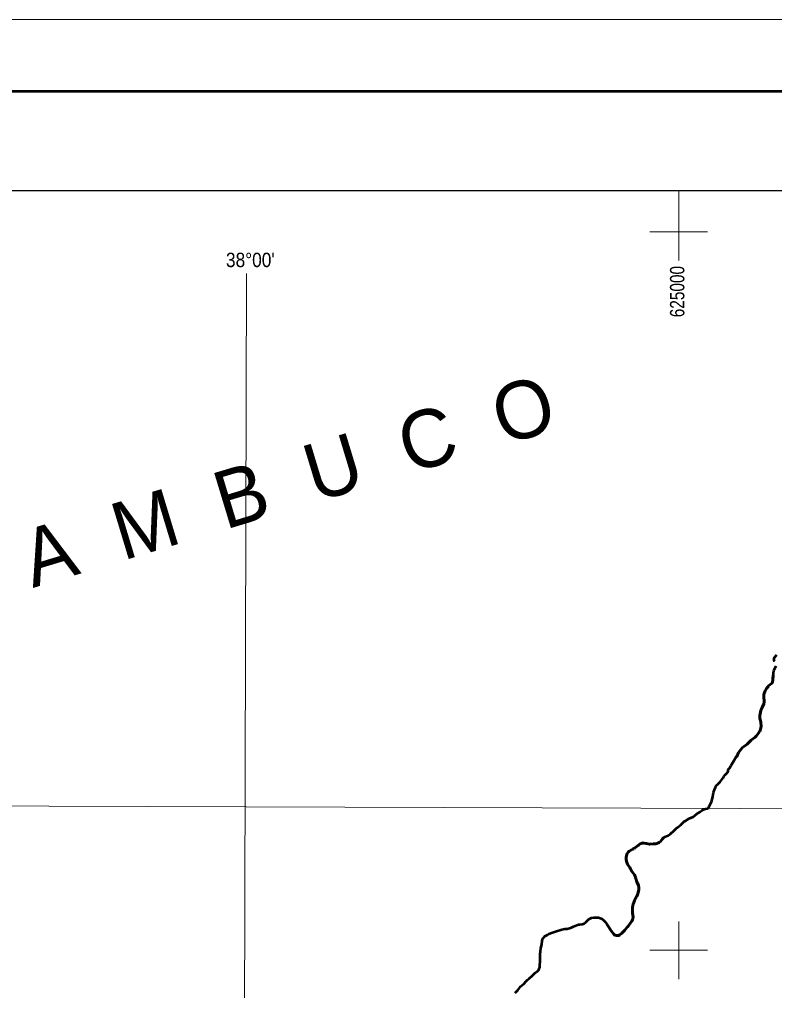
# Model space of a CAD drawing. Extents: x 553962 to 842807, y 8883888 to 9032388.
# Drawn here: x 602069 to 628336, y 8998597 to 9032388 of the extents above; entities that cross this region are included whole.
import ezdxf
from ezdxf.enums import TextEntityAlignment as Align

# ---------------------------------------------------------------- set-up
doc = ezdxf.new("R2010")
doc.units = 0
doc.header["$LTSCALE"] = 20
doc.linetypes.add('LONG_DASH_SHORT_DASH', pattern=[9.9, 6, -1.2, 1.5, -1.2])
for name, color, linetype, lineweight in [('1', 7, 'Continuous', 13), ('2', 7, 'Continuous', 13), ('24', 7, 'Continuous', 25), ('3', 7, 'Continuous', 13), ('7', 7, 'LONG_DASH_SHORT_DASH', 60)]:
    doc.layers.add(name, color=color, linetype=linetype, lineweight=lineweight)
for name, color, linetype in [('42', 7, 'Continuous'), ('46', 7, 'Continuous'), ('47', 7, 'Continuous')]:
    doc.layers.add(name, color=color, linetype=linetype)

msp = doc.modelspace()

# ---------------------------------------------------------------- linework, layer by layer
at = {"layer": '1'}
for points in [[(609971.86, 9023551.79), (609764.7, 8949706.73), (609734.23, 8939404.42)], [(565303.24, 9005146.57), (664889.8, 9004806.7), (719872.1, 9004543.9), (790635.75, 9004109.02)]]:
    msp.add_lwpolyline(points, dxfattribs=at)
at = {"layer": '2'}
for p, q in [((625000, 9024000), (625000, 9026438.81)), ((624000, 9025000), (626000, 9025000)), ((625000, 8999000), (625000, 9001000)), ((624000, 9000000), (626000, 9000000))]:
    msp.add_line(p, q, dxfattribs=at)
at = {"layer": '24', "lineweight": 53}
for points in [[(628342.78, 9010045.26), (628316.93, 9010072.44), (628322.96, 9010177.8), (628415.6, 9010283.43)], [(626724.96, 9006288.39), (626779.05, 9006348.76), (626819.96, 9006414.73), (626852.08, 9006473.14), (626884.18, 9006537.2), (626914.49, 9006591.85), (626995.85, 9006730.36), (627000.85, 9006736.02), (627018.21, 9006741.72), (627021.98, 9006744.56), (627029.99, 9006769.03), (627091.74, 9006889.62), (627130.85, 9006942.41), (627168.48, 9006998.97), (627205.73, 9007042.35), (627264.54, 9007088.63), (627329.99, 9007129.28), (627383.44, 9007169.9), (627473.63, 9007266.13), (627521.75, 9007311.43), (627580.78, 9007360.53), (627647.39, 9007407.77), (627691.02, 9007452.12), (627741.18, 9007504.95), (627838.24, 9007649.16), (627862.83, 9007736.7), (627868.93, 9007802.56), (627855.56, 9007930.42), (627843.13, 9007991.51), (627825.88, 9008062.92), (627820.09, 9008114.63), (627822.97, 9008171.07), (627839.08, 9008232.25), (627861.62, 9008347.06), (627883.52, 9008403.56), (627919.6, 9008464.81), (627956.33, 9008574.97), (627969.51, 9008644.61), (627969.31, 9008703.86), (627962.7, 9008772.49), (627962.99, 9008898.51), (627984.75, 9008964.42), (628013.5, 9009025.64), (628060.56, 9009104.8), (628118.98, 9009194.33), (628125.34, 9009200.94), (628181.51, 9009242.5), (628249.38, 9009298.22), (628267.16, 9009335.89), (628279.36, 9009398.94), (628279.5, 9009462.9), (628282.37, 9009524.98), (628295.34, 9009656.69), (628310.9, 9009719.75), (628332.67, 9009781.89), (628390, 9009900.58)], [(626160.95, 9005249.19), (626188.61, 9005351.79), (626211.55, 9005488.24), (626262.03, 9005621.95), (626290.83, 9005686), (626318.12, 9005740.63), (626357.15, 9005784.02), (626440.49, 9005861.42), (626481.11, 9005905.75), (626516.29, 9005951.01), (626547.5, 9005998.14), (626576.47, 9006046.2), (626606.58, 9006087.68), (626651.27, 9006133.91), (626697.18, 9006185.79), (626721.09, 9006227.25), (626724.96, 9006288.39)], [(626020.34, 9004931.64), (626138.36, 9005165.41), (626160.95, 9005249.19)], [(624968.65, 9004287.4), (625077.4, 9004367.4), (625125.27, 9004407.39), (625196.08, 9004475.39), (625231.96, 9004503.39), (625369.33, 9004583.38), (625507.02, 9004648.37), (625552.21, 9004680.37), (625627.27, 9004743.36), (625747.46, 9004813.36), (625804.83, 9004859.35), (625863.64, 9004898.35), (625936.48, 9004925.74), (626020.34, 9004931.64)], [(622356.06, 9001071.57), (622438.87, 9000988.57), (622501.25, 9000910.57), (622651.63, 9000673.56), (622694.76, 9000613.56), (622741.88, 9000562.56), (622781.57, 9000528.56), (622837.95, 9000513.56), (622887.51, 9000510.55), (622903.45, 9000513.55), (622951.51, 9000538.55), (623008.32, 9000580.55), (623061.07, 9000626.54), (623124.51, 9000694.54), (623279.19, 9000880.53), (623385.01, 9001031.52), (623398.19, 9001059.52), (623411.19, 9001147.52), (623406.06, 9001224.52), (623394.5, 9001300.52), (623396.87, 9001485.52), (623407.75, 9001557.51), (623420.68, 9001604.51), (623474.81, 9001753.51), (623546.49, 9001882.5), (623566.49, 9001928.5), (623606.36, 9002057.5), (623614.43, 9002114.5), (623615.17, 9002180.5), (623603.61, 9002252.5), (623548.86, 9002380.5), (623488.73, 9002579.5), (623465.35, 9002623.5), (623431.17, 9002675.5), (623387.35, 9002730.5), (623301.97, 9002882.5), (623235.1, 9002973.51), (623183.34, 9003094.51), (623167.72, 9003160.51), (623169.97, 9003229.51), (623186.59, 9003301.5), (623209.96, 9003362.5), (623241.9, 9003412.5), (623274.84, 9003442.5), (623462.09, 9003547.49), (623608.78, 9003667.48), (623666.15, 9003700.48), (623727.15, 9003726.47), (623755.59, 9003733.47), (623782.53, 9003731.47), (623993.46, 9003691.46), (624127.15, 9003701.45), (624208.97, 9003698.45), (624301.4, 9003736.44), (624324.65, 9003751.44), (624377.4, 9003798.44), (624433.03, 9003873.44), (624469.53, 9003912.43), (624514.84, 9003941.43), (624628.9, 9003992.42), (624709.53, 9004038.42), (624743.9, 9004077.42), (624810.59, 9004137.41), (624900.27, 9004230.41), (624967.96, 9004288.4)], [(620148.26, 8999353.71), (620168.57, 8999417.7), (620186.76, 8999678.7), (620178.07, 8999819.7), (620178.5, 8999880.7), (620194.32, 8999957.7), (620208.25, 9000078.69), (620242.75, 9000202.69), (620252.87, 9000329.69), (620263.25, 9000378.69), (620280.06, 9000412.69), (620305.31, 9000447.68), (620344.5, 9000485.68), (620432.56, 9000539.68), (620488.93, 9000569.67), (620581.62, 9000610.67), (620710.49, 9000657.66), (620939.43, 9000718.65), (621042.25, 9000740.64), (621118.37, 9000748.64), (621242.18, 9000776.63), (621275.5, 9000790.63), (621342.12, 9000826.63), (621518.25, 9000894.62), (621561.06, 9000901.62), (621637.25, 9000903.61), (621689.56, 9000916.61), (621716.56, 9000931.61), (621774.62, 9000977.6), (621867.24, 9001066.6), (621924.68, 9001110.59), (621967.49, 9001129.59), (622048.62, 9001140.59), (622160.31, 9001143.58), (622215.18, 9001136.58), (622300.12, 9001105.58), (622356.06, 9001071.57)], [(619310.27, 8998518.76), (619402.77, 8998610.75), (619472.9, 8998704.75), (619501.71, 8998736.74), (619608.14, 8998826.74), (619700.33, 8998928.73), (619746.89, 8998966.73), (619804.33, 8999021.73), (619907.58, 8999106.72), (619970.08, 8999177.72), (620010.26, 8999215.71), (620083.76, 8999267.71), (620109.08, 8999292.71), (620148.26, 8999353.71), (620148.26, 8999353.71)]]:
    msp.add_lwpolyline(points, dxfattribs=at)
at = {"layer": '3'}
msp.add_lwpolyline([(842807.26, 9032387.81), (842807.26, 8883887.81), (553961.7, 8883887.81), (553961.7, 9032387.81)], close=True, dxfattribs=at)
at = {"layer": '3', "lineweight": 53}
msp.add_lwpolyline([(840307.26, 9029887.81), (840307.26, 8886387.81), (560211.7, 8886387.81), (560211.7, 9029887.81)], close=True, dxfattribs=at)
at = {"layer": '3', "lineweight": 25}
msp.add_lwpolyline([(563033.89, 9026438.81), (793061.13, 9026438.81), (793495.55, 8889836.82), (563468.3, 8889836.82)], close=True, dxfattribs=at)
at = {"layer": '7'}
for points in [[(626959.99, 9006669.31), (626995.85, 9006730.36), (627000.85, 9006736.02), (627018.21, 9006741.72), (627021.98, 9006744.56), (627029.99, 9006769.03), (627091.74, 9006889.62), (627130.85, 9006942.41), (627168.48, 9006998.97), (627205.73, 9007042.35), (627264.54, 9007088.63), (627329.99, 9007129.28), (627383.44, 9007169.9), (627473.63, 9007266.13), (627521.75, 9007311.43), (627580.78, 9007360.53), (627647.39, 9007407.77), (627691.02, 9007452.12), (627741.18, 9007504.95), (627838.24, 9007649.16), (627862.83, 9007736.7), (627868.93, 9007802.56), (627855.56, 9007930.42), (627843.13, 9007991.51), (627825.88, 9008062.92), (627820.09, 9008114.63), (627822.97, 9008171.07), (627839.08, 9008232.25), (627861.62, 9008347.06), (627883.52, 9008403.56), (627919.6, 9008464.81), (627956.33, 9008574.97), (627969.51, 9008644.61), (627969.31, 9008703.86), (627962.7, 9008772.49), (627962.99, 9008898.51), (627984.75, 9008964.42), (628013.5, 9009025.64), (628060.56, 9009104.8), (628118.98, 9009194.33), (628125.34, 9009200.94), (628181.51, 9009242.5), (628249.38, 9009298.22), (628267.16, 9009335.89), (628279.36, 9009398.94), (628279.5, 9009462.9), (628282.37, 9009524.98), (628286.63, 9009568.23)], [(622572.21, 9000798.74), (622651.63, 9000673.56), (622694.76, 9000613.56), (622741.88, 9000562.56), (622781.57, 9000528.56), (622837.95, 9000513.56), (622887.51, 9000510.55), (622903.45, 9000513.55), (622951.51, 9000538.55), (623008.32, 9000580.55), (623061.07, 9000626.54), (623124.51, 9000694.54), (623279.19, 9000880.53), (623385.01, 9001031.52), (623398.19, 9001059.52), (623411.19, 9001147.52), (623406.06, 9001224.52), (623394.5, 9001300.52), (623396.87, 9001485.52), (623407.75, 9001557.51), (623420.68, 9001604.51), (623474.81, 9001753.51), (623546.49, 9001882.5), (623566.49, 9001928.5), (623606.36, 9002057.5), (623614.43, 9002114.5), (623615.17, 9002180.5), (623603.61, 9002252.5), (623548.86, 9002380.5), (623488.73, 9002579.5), (623465.35, 9002623.5), (623431.17, 9002675.5), (623387.35, 9002730.5), (623301.97, 9002882.5), (623235.1, 9002973.51), (623183.34, 9003094.51), (623167.72, 9003160.51), (623169.97, 9003229.51), (623186.59, 9003301.5), (623209.96, 9003362.5), (623241.9, 9003412.5), (623274.84, 9003442.5), (623462.09, 9003547.49), (623608.78, 9003667.48), (623666.15, 9003700.48), (623727.15, 9003726.47), (623755.59, 9003733.47), (623782.53, 9003731.47), (623993.46, 9003691.46), (624127.15, 9003701.45), (624208.97, 9003698.45), (624301.4, 9003736.44), (624324.65, 9003751.44), (624377.4, 9003798.44), (624433.03, 9003873.44), (624469.53, 9003912.43), (624514.84, 9003941.43)]]:
    msp.add_lwpolyline(points, dxfattribs=at)

# ---------------------------------------------------------------- texts
at = {"layer": '42'}
msp.add_text('P  E  R  N  A  M  B  U  C  O', height=2000, rotation=16.855, dxfattribs=at).set_placement((589730.89, 9008723.54))
at = {"layer": '46', "width": 0.9}
msp.add_text("38°00'", height=500, dxfattribs=at).set_placement((610099.91, 9023770.43), align=Align.CENTER)
at = {"layer": '47', "width": 0.8}
msp.add_text('625000', height=500, rotation=90, dxfattribs=at).set_placement((625197.28, 9022917.37), align=Align.CENTER)

doc.saveas('drawing.dxf')
